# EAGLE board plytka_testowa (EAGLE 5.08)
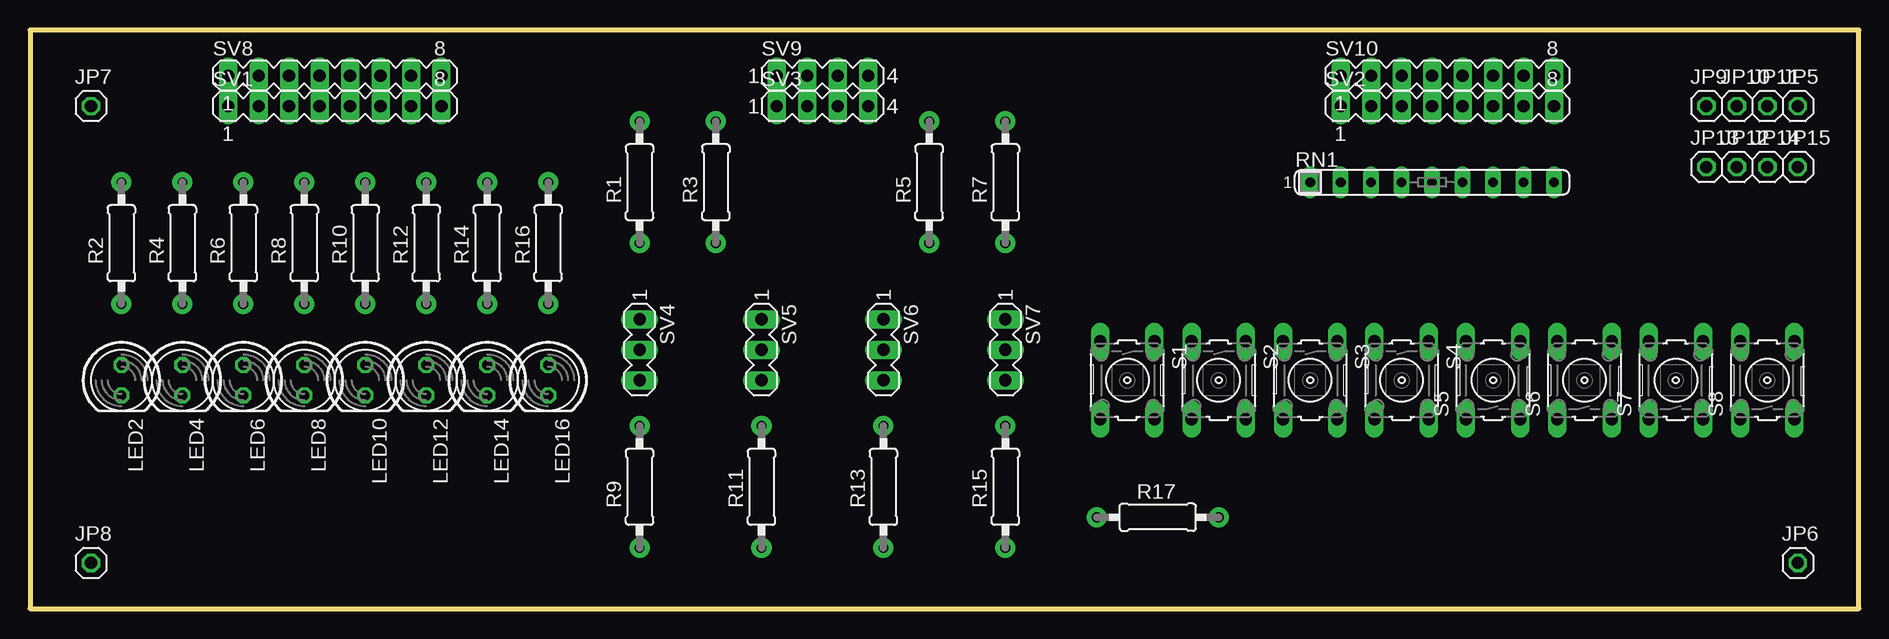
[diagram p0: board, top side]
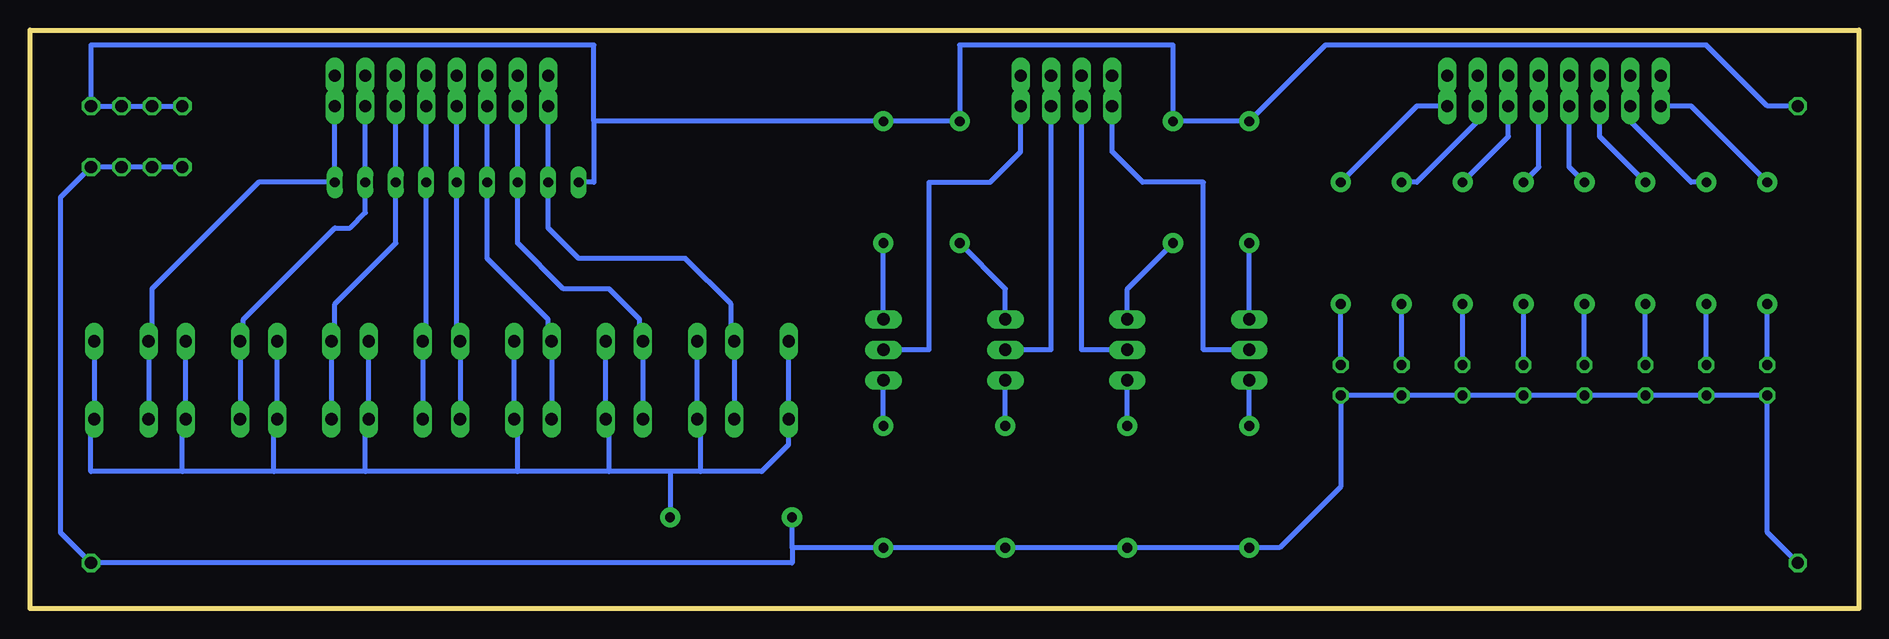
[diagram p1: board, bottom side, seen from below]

Size 152.4 x 48.26 mm. Coordinates in mm from the lower left corner, seen from the top.
Outline: 0,0 152.4,0 152.4,48.26 0,48.26 0,0
Copper layers (1*16): Top 0.035mm / dielectric 1.5mm / Bottom 0.035mm
Design rules "default": minimum track width 10mil, minimum drill 24mil, track to track 8mil, track to pad 8mil, pad to pad 8mil, via to via 8mil, smd to smd 8mil, copper to edge 40mil, drill to drill 8mil, minimum pad ring 10mil, minimum via ring 8mil, stop-mask expansion 4mil, vias tented up to drill 0mil, thermal gap 10mil

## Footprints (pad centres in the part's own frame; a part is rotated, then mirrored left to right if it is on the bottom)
1X01 = drill 1.016 octagon: 1 0,0
LED5MM = drill 0.813 octagon: A -1.27,0; K 1.27,0
0207/10 = drill 0.813 pad 1.676 round: 1 -5.08,0; 2 5.08,0
SIL9 = drill 0.813 long: 1 -10.16,0; 2 -7.62,0; 3 -5.08,0; 4 -2.54,0; 5 0,0; 6 2.54,0; 7 5.08,0; 8 7.62,0; 9 10.16,0
B3F-10XX = drill 1.016 long: 1 -3.251,2.261; 2 3.251,2.261; 3 -3.251,-2.261; 4 3.251,-2.261
MA08-1 = drill 1.016 long: 1 -8.89,0; 2 -6.35,0; 3 -3.81,0; 4 -1.27,0; 5 1.27,0; 6 3.81,0; 7 6.35,0; 8 8.89,0
MA04-1 = drill 1.016 long: 1 -3.81,0; 2 -1.27,0; 3 1.27,0; 4 3.81,0
MA03-1 = drill 1.016 long: 1 -2.54,0; 2 0,0; 3 2.54,0

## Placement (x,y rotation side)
JP5  [1X01]  147.32,41.91 0 top
JP6  [1X01]  147.32,3.81 0 top
JP7  [1X01]  5.08,41.91 0 top
JP8  [1X01]  5.08,3.81 0 top
JP9  [1X01]  139.7,41.91 0 top
JP10  [1X01]  142.24,41.91 0 top
JP11  [1X01]  144.78,41.91 0 top
JP12  [1X01]  142.24,36.83 0 top
JP13  [1X01]  139.7,36.83 0 top
JP14  [1X01]  144.78,36.83 0 top
JP15  [1X01]  147.32,36.83 0 top
LED2  [LED5MM]  7.62,19.05 270 top
LED4  [LED5MM]  12.7,19.05 270 top
LED6  [LED5MM]  17.78,19.05 270 top
LED8  [LED5MM]  22.86,19.05 270 top
LED10  [LED5MM]  27.94,19.05 270 top
LED12  [LED5MM]  33.02,19.05 270 top
LED14  [LED5MM]  38.1,19.05 270 top
LED16  [LED5MM]  43.18,19.05 270 top
R1  [0207/10]  50.8,35.56 90 top
R2  [0207/10]  7.62,30.48 90 top
R3  [0207/10]  57.15,35.56 90 top
R4  [0207/10]  12.7,30.48 90 top
R5  [0207/10]  74.93,35.56 90 top
R6  [0207/10]  17.78,30.48 90 top
R7  [0207/10]  81.28,35.56 90 top
R8  [0207/10]  22.86,30.48 90 top
R9  [0207/10]  50.8,10.16 90 top
R10  [0207/10]  27.94,30.48 90 top
R11  [0207/10]  60.96,10.16 90 top
R12  [0207/10]  33.02,30.48 90 top
R13  [0207/10]  71.12,10.16 90 top
R14  [0207/10]  38.1,30.48 90 top
R15  [0207/10]  81.28,10.16 90 top
R16  [0207/10]  43.18,30.48 90 top
R17  330  [0207/10]  93.98,7.62 0 top
RN1  [SIL9]  116.84,35.56 0 top
S1  [B3F-10XX]  91.44,19.05 270 top
S2  [B3F-10XX]  99.06,19.05 270 top
S3  [B3F-10XX]  106.68,19.05 270 top
S4  [B3F-10XX]  114.3,19.05 270 top
S5  [B3F-10XX]  121.92,19.05 90 top
S6  [B3F-10XX]  129.54,19.05 90 top
S7  [B3F-10XX]  137.16,19.05 90 top
S8  [B3F-10XX]  144.78,19.05 90 top
SV1  [MA08-1]  25.4,41.91 0 top
SV2  [MA08-1]  118.11,41.91 0 top
SV3  [MA04-1]  66.04,41.91 0 top
SV4  [MA03-1]  50.8,21.59 270 top
SV5  [MA03-1]  60.96,21.59 270 top
SV6  [MA03-1]  71.12,21.59 270 top
SV7  [MA03-1]  81.28,21.59 270 top
SV8  [MA08-1]  25.4,44.45 0 top
SV9  [MA04-1]  66.04,44.45 0 top
SV10  [MA08-1]  118.11,44.45 0 top

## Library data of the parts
JP5-JP15 = !pinhead
LED2 LED4 LED6 LED8 LED10 LED12 LED14 LED16 = led
R1-R17 = !rcl_mod
RN1 = resistor-sil
S1-S8 = switch-omron
SV1-SV10 = !con-lstb

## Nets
+5V: JP5.1 JP7.1 JP9.1 JP10.1 JP11.1 R1.2 R3.2 R5.2 R7.2 RN1.1
GND: JP6.1 JP8.1 JP12.1 JP13.1 JP14.1 JP15.1 LED2.K LED4.K LED6.K LED8.K LED10.K LED12.K LED14.K LED16.K R9.1 R11.1 R13.1 R15.1 R17.1
N$1: R2.2 SV1.1 SV8.1
N$2: LED2.A R2.1
N$3: R4.2 SV1.2 SV8.2
N$4: LED4.A R4.1
N$5: R6.2 SV1.3 SV8.3
N$6: LED6.A R6.1
N$7: R8.2 SV1.4 SV8.4
N$8: LED8.A R8.1
N$9: R10.2 SV1.5 SV8.5
N$10: LED10.A R10.1
N$11: R12.2 SV1.6 SV8.6
N$12: LED12.A R12.1
N$13: R14.2 SV1.7 SV8.7
N$14: LED14.A R14.1
N$15: R16.2 SV1.8 SV8.8
N$16: LED16.A R16.1
N$17: SV3.1 SV4.2 SV9.1
N$18: SV3.2 SV5.2 SV9.2
N$19: SV3.3 SV6.2 SV9.3
N$20: SV3.4 SV7.2 SV9.4
N$21: R1.1 SV4.1
N$22: R9.2 SV4.3
N$23: R11.2 SV5.3
N$24: R3.1 SV5.1
N$25: R5.1 SV6.1
N$26: R13.2 SV6.3
N$27: R15.2 SV7.3
N$28: R7.1 SV7.1
N$30: RN1.2 S1.1 S1.2 SV2.1 SV10.1
N$31: RN1.3 S2.1 S2.2 SV2.2 SV10.2
N$32: RN1.4 S3.1 S3.2 SV2.3 SV10.3
N$33: RN1.5 S4.1 S4.2 SV2.4 SV10.4
N$34: RN1.6 S5.1 S5.2 SV2.5 SV10.5
N$35: RN1.7 S6.1 S6.2 SV2.6 SV10.6
N$36: RN1.8 S7.1 S7.2 SV2.7 SV10.7
N$37: RN1.9 S8.1 S8.2 SV2.8 SV10.8
N$38: R17.2 S1.3 S1.4 S2.3 S2.4 S3.3 S3.4 S4.3 S4.4 S5.3 S5.4 S6.3 S6.4 S7.3 S7.4 S8.3 S8.4

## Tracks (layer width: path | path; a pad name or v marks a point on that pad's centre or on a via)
+5V
  Bottom 0.406: 105.41,40.64 105.41,46.99 147.32,46.99 JP5.1 JP11.1 JP10.1 JP9.1 | RN1.1 105.41,35.56 105.41,40.64 | 105.41,40.64 R7.2 R5.2 74.93,46.99 57.15,46.99 R3.2 R1.2 44.45,46.99 12.7,46.99 7.62,41.91 JP7.1
GND
  Bottom 0.406: 88.9,5.08 88.9,3.81 JP6.1 149.86,6.35 149.86,34.29 JP15.1 JP14.1 JP12.1 JP13.1 | 88.9,5.08 R17.1 | 88.9,5.08 R15.1 R13.1 R11.1 R9.1 48.26,5.08 43.18,10.16 LED16.K LED14.K LED12.K LED10.K LED8.K LED6.K LED4.K LED2.K 7.62,6.35 JP8.1
N$1
  Bottom 0.406: R2.2 13.97,41.91 SV1.1 SV8.1
N$2
  Bottom 0.406: LED2.A R2.1
N$3
  Bottom 0.406: R4.2 13.97,35.56 19.05,40.64 SV1.2 SV8.2
N$4
  Bottom 0.406: LED4.A R4.1
N$5
  Bottom 0.406: R6.2 21.59,39.37 SV1.3 SV8.3
N$6
  Bottom 0.406: LED6.A R6.1
N$7
  Bottom 0.406: R8.2 24.13,36.83 SV1.4 SV8.4
N$8
  Bottom 0.406: LED8.A R8.1
N$9
  Bottom 0.406: R10.2 26.67,36.83 SV1.5 SV8.5
N$10
  Bottom 0.406: LED10.A R10.1
N$11
  Bottom 0.406: R12.2 29.21,39.37 SV1.6 SV8.6
N$12
  Bottom 0.406: LED12.A R12.1
N$13
  Bottom 0.406: R14.2 36.83,35.56 31.75,40.64 SV1.7 SV8.7
N$14
  Bottom 0.406: LED14.A R14.1
N$15
  Bottom 0.406: R16.2 36.83,41.91 SV1.8 SV8.8
N$16
  Bottom 0.406: LED16.A R16.1
N$17
  Bottom 0.406: SV4.2 54.61,21.59 54.61,35.56 59.69,35.56 62.23,38.1 SV3.1 SV9.1
N$18
  Bottom 0.406: SV5.2 64.77,21.59 SV3.2 SV9.2
N$19
  Bottom 0.406: SV6.2 67.31,21.59 SV3.3 SV9.3
N$20
  Bottom 0.406: SV7.2 77.47,21.59 77.47,35.56 72.39,35.56 69.85,38.1 SV3.4 SV9.4
N$21
  Bottom 0.406: SV4.1 R1.1
N$22
  Bottom 0.406: R9.2 SV4.3
N$23
  Bottom 0.406: R11.2 SV5.3
N$24
  Bottom 0.406: SV5.1 60.96,26.67 R3.1
N$25
  Bottom 0.406: SV6.1 71.12,26.67 R5.1
N$26
  Bottom 0.406: R13.2 SV6.3
N$27
  Bottom 0.406: R15.2 SV7.3
N$28
  Bottom 0.406: SV7.1 R7.1
N$30
  Bottom 0.406: SV10.1 SV2.1 RN1.2 109.22,31.75 106.68,29.21 97.79,29.21 93.98,25.4 93.98,22.58 S1.1 S1.2
N$31
  Bottom 0.406: SV10.2 SV2.2 RN1.3 111.76,30.48 107.95,26.67 104.14,26.67 101.6,24.13 101.6,22.58 S2.1 S2.2
N$32
  Bottom 0.406: SV10.3 SV2.3 RN1.4 114.3,29.21 109.22,24.13 109.22,22.58 S3.1 S3.2
N$33
  Bottom 0.406: SV10.4 SV2.4 RN1.5 116.84,22.58 S4.1 S4.2
N$34
  Bottom 0.406: SV10.5 SV2.5 RN1.6 119.38,22.58 S5.2 S5.1
N$35
  Bottom 0.406: SV10.6 SV2.6 RN1.7 121.92,30.48 127,25.4 127,22.58 S6.2 S6.1
N$36
  Bottom 0.406: SV10.7 SV2.7 RN1.8 124.46,33.02 125.73,31.75 127,31.75 134.62,24.13 134.62,22.58 S7.2 S7.1
N$37
  Bottom 0.406: SV10.8 SV2.8 RN1.9 133.35,35.56 142.24,26.67 142.24,22.58 S8.2 S8.1
N$38
  Bottom 0.406: 96.52,11.43 91.44,11.43 89.18,13.69 S1.4 S1.3 | 96.52,11.43 96.52,15.52 S2.4 S2.3 | 96.52,11.43 99.06,11.43 | 99.06,11.43 104.14,11.43 | 104.14,11.43 104.14,15.52 S3.4 S3.3 | 111.76,11.43 111.76,15.24 112.04,15.52 S4.4 S4.3 | 104.14,11.43 111.76,11.43 | 124.46,11.43 124.46,15.24 124.18,15.52 S5.3 S5.4 | 111.76,11.43 124.46,11.43 | 132.08,11.43 132.08,15.24 131.8,15.52 S6.3 S6.4 | 124.46,11.43 132.08,11.43 | 139.7,11.43 139.7,15.24 139.42,15.52 S7.3 S7.4 | 132.08,11.43 139.7,11.43 | 139.7,11.43 147.32,11.43 147.32,15.24 147.04,15.52 S8.3 S8.4 | 99.06,11.43 R17.2

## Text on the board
Document: +5V | +5V | 1 | 2 | 3 | 4 | 5 | 6 | 7 | 8 | 1 | 2 | 3 | 4 | 1 | 2 | 3 | 4 | 5 | 6 | 7 | 8 | GND | 1 | 1 | 1 | 1 | 0 | 0 | 0 | 0 | 1 | 1 | 1 | 2 | 3 | 4 | 2 | 3 | 4 | 5 | 6 | 7 | 8 | 2 | 3 | 4 | 5 | 6 | 7 | 8 | GND | GND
